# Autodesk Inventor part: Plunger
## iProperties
Created: 2009-03
Part Number: Plunger
Document SubType Name: Modeling
Designer: tangg
Density: 8.03 g/cm^3
Material: Stainless Steel, Austenitic
Mass: 116.743 g
Surface Area: 101.946 cm^2
Volume: 14.5383 cm^3
Author: tangg
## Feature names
1. Sweep1
2. Revolution1
3. Chamfer1
4. Split7
5. Split8
6. Split9
